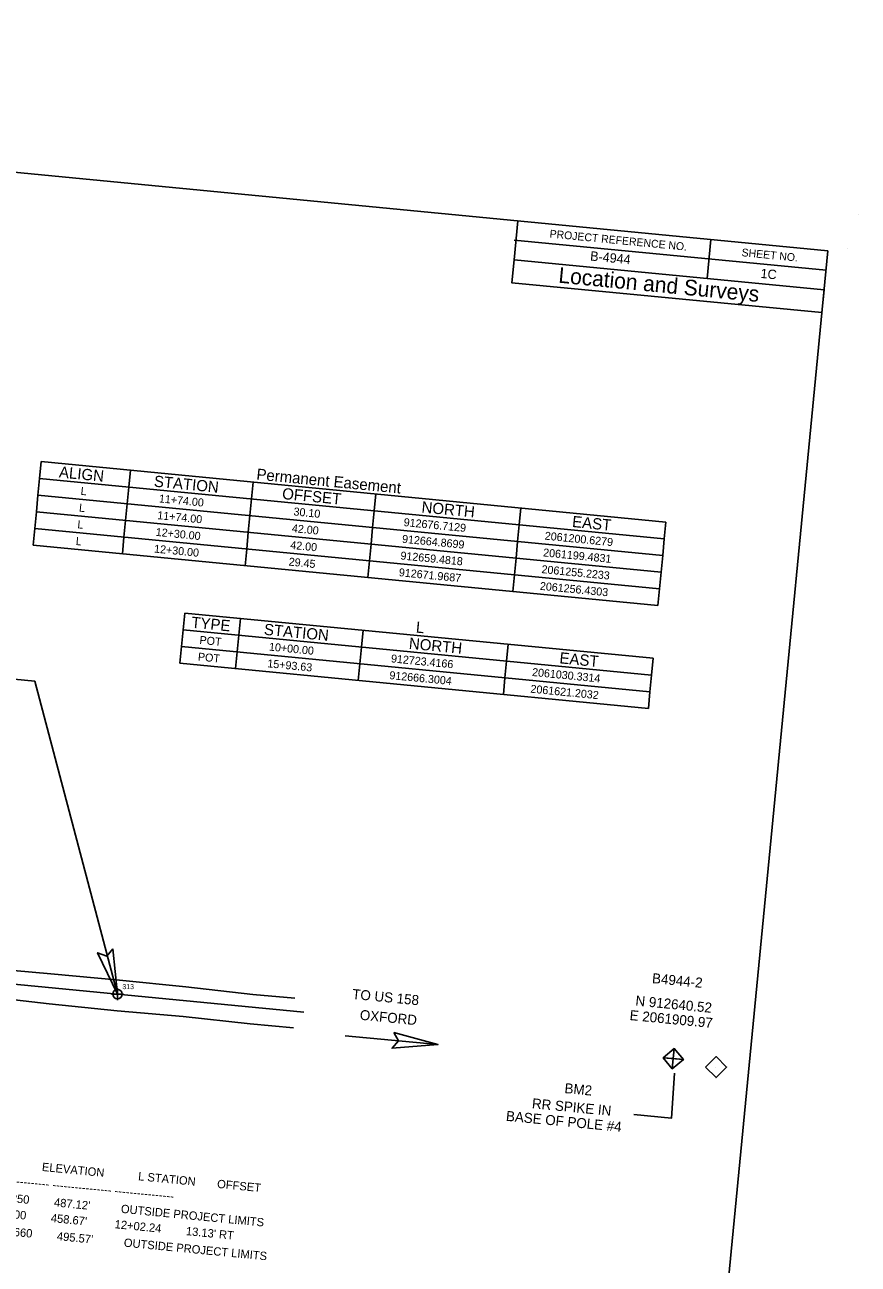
# Model space of a CAD drawing. Extents: x 2060504 to 2061945, y 912229 to 913160.
# Drawn here: x 2061482 to 2061898, y 912540 to 913160 of the extents above; entities that cross this region are included whole.
import ezdxf

# ---------------------------------------------------------------- set-up
doc = ezdxf.new("R2010")
doc.units = 0
for name, color, linetype in [('COGO Default Chain', 7, 'Continuous'), ('Cogo Default Point CELL', 7, 'Continuous'), ('COGO Default Point Number', 7, 'Continuous'), ('CTL Bench Mark CELL', 7, 'Continuous'), ('CTL Bench Mark Leader', 7, 'Continuous'), ('CTL Bench Mark Text', 7, 'Continuous'), ('CTL Sheet Border CELL', 7, 'Continuous'), ('CTL Sheet Notes CELL', 7, 'Continuous'), ('CTL Sheet Table Cell', 7, 'Continuous'), ('CTL Sheet Text', 7, 'Continuous'), ('CTL Supplemental Horizontal and Vertical CELL', 7, 'Continuous'), ('CTL Supplemental Horizontal and Vertical Text', 7, 'Continuous'), ('Exist Horizontal Alignment', 7, 'Continuous'), ('Exist Roads Soil', 7, 'Continuous'), ('Prop Terminator CELL', 7, 'Continuous'), ('Sheet Data Field CELL', 7, 'Continuous')]:
    doc.layers.add(name, color=color, linetype=linetype)

# ---------------------------------------------------------------- blocks, each defined once
blk = doc.blocks.new('COGO DEFAULT POINT')
at = {"layer": 'Cogo Default Point CELL'}
for points in [[(-0.06, 0), (0, 0)], [(0, 0.06), (0, 0)], [(0, 0), (0.06, 0)], [(0, 0), (0, -0.06)]]:
    blk.add_lwpolyline(points, dxfattribs=at)
blk.add_circle((0, 0), 0.0469, dxfattribs=at)

msp = doc.modelspace()

# ---------------------------------------------------------------- linework, layer by layer
at = {"layer": 'COGO Default Chain'}
msp.add_line((2061030.33, 912723.42), (2061621.2, 912666.3), dxfattribs=at)
at = {"layer": 'CTL Bench Mark CELL'}
msp.add_line((2061805.75, 912643.06), (2061805.75, 912643.06), dxfattribs=at)
msp.add_lwpolyline([(2061800.69, 912643.54), (2061806.23, 912648.11), (2061810.8, 912642.57), (2061805.26, 912638)], close=True, dxfattribs=at)
for points in [[(2061806.23, 912648.11), (2061805.26, 912638), (2061805.74, 912643.06), (2061810.8, 912642.57), (2061800.69, 912643.54)], [(2061805.74, 912643.06), (2061806.23, 912648.11), (2061800.69, 912643.54), (2061805.74, 912643.06)], [(2061805.74, 912643.06), (2061805.26, 912638), (2061810.8, 912642.57), (2061805.74, 912643.06)]]:
    msp.add_lwpolyline(points, dxfattribs=at)
at = {"layer": 'CTL Bench Mark Leader'}
msp.add_lwpolyline([(2061806.34, 912635.72), (2061804.9, 912613.3), (2061786.04, 912615.13)], dxfattribs=at)
at = {"layer": 'CTL Sheet Border CELL'}
for p, q in [((2061898.13, 913065.22), (2061898.13, 913065.22)), ((2061728.05, 913061.97), (2061726.16, 913042.5)), ((2061726.22, 913052.31), (2061882.06, 913037.25)), ((2061824.58, 913052.64), (2061822.7, 913033.17)), ((2061892.94, 913048.08), (2061892.94, 913048.08)), ((2061892.94, 913048.08), (2061892.94, 913048.08))]:
    msp.add_line(p, q, dxfattribs=at)
for points in [[(2061883, 913047.03), (2060714.54, 913159.97), (2060635.47, 912342.05), (2061803.94, 912229.1)], [(2061726.16, 913042.5), (2061881.12, 913027.52), (2061880.01, 913016.05), (2061725.06, 913031.03)]]:
    msp.add_lwpolyline(points, close=True, dxfattribs=at)
at = {"layer": 'CTL Sheet Table Cell'}
for p, q in [((2061489.92, 912941.54), (2061489.11, 912933.18)), ((2061489.92, 912941.54), (2061802.07, 912911.37)), ((2061534.51, 912937.23), (2061533.7, 912928.87)), ((2061489.11, 912933.18), (2061488.3, 912924.82)), ((2061489.11, 912933.18), (2061801.26, 912903.01)), ((2061533.7, 912928.87), (2061532.9, 912920.51)), ((2061595.83, 912931.31), (2061595.02, 912922.95)), ((2061488.3, 912924.82), (2061487.5, 912916.46)), ((2061488.3, 912924.82), (2061800.45, 912894.65)), ((2061595.02, 912922.95), (2061594.21, 912914.58)), ((2061657.14, 912925.38), (2061656.33, 912917.02)), ((2061487.5, 912916.46), (2061486.69, 912908.1)), ((2061487.5, 912916.46), (2061799.64, 912886.29)), ((2061532.9, 912920.51), (2061532.09, 912912.15)), ((2061656.33, 912917.02), (2061655.52, 912908.66)), ((2061729.6, 912918.38), (2061728.79, 912910.01)), ((2061532.09, 912912.15), (2061531.28, 912903.79)), ((2061594.21, 912914.58), (2061593.4, 912906.22)), ((2061728.79, 912910.01), (2061727.99, 912901.65)), ((2061802.07, 912911.37), (2061801.26, 912903.01)), ((2061486.69, 912908.1), (2061485.88, 912899.74)), ((2061486.69, 912908.1), (2061798.83, 912877.93)), ((2061531.28, 912903.79), (2061530.47, 912895.43)), ((2061593.4, 912906.22), (2061592.59, 912897.86)), ((2061655.52, 912908.66), (2061654.72, 912900.3)), ((2061801.26, 912903.01), (2061800.45, 912894.65)), ((2061485.88, 912899.74), (2061798.02, 912869.57)), ((2061592.59, 912897.86), (2061591.79, 912889.5)), ((2061654.72, 912900.3), (2061653.91, 912891.94)), ((2061727.99, 912901.65), (2061727.18, 912893.29)), ((2061653.91, 912891.94), (2061653.1, 912883.57)), ((2061727.18, 912893.29), (2061726.37, 912884.93)), ((2061800.45, 912894.65), (2061799.64, 912886.29)), ((2061726.37, 912884.93), (2061725.56, 912876.57)), ((2061799.64, 912886.29), (2061798.83, 912877.93)), ((2061798.83, 912877.93), (2061798.02, 912869.57)), ((2061561.62, 912865.85), (2061560.81, 912857.49)), ((2061561.62, 912865.85), (2061795.73, 912843.22)), ((2061589.49, 912863.16), (2061588.68, 912854.79)), ((2061560.81, 912857.49), (2061560, 912849.13)), ((2061560.81, 912857.49), (2061794.92, 912834.86)), ((2061588.68, 912854.79), (2061587.87, 912846.43)), ((2061650.8, 912857.23), (2061650, 912848.87)), ((2061560, 912849.13), (2061559.2, 912840.77)), ((2061560, 912849.13), (2061794.11, 912826.5)), ((2061650, 912848.87), (2061649.19, 912840.51)), ((2061723.27, 912850.22), (2061722.46, 912841.86)), ((2061587.87, 912846.43), (2061587.07, 912838.07)), ((2061722.46, 912841.86), (2061721.65, 912833.5)), ((2061795.73, 912843.22), (2061794.92, 912834.86)), ((2061559.2, 912840.77), (2061793.3, 912818.14)), ((2061649.19, 912840.51), (2061648.38, 912832.15)), ((2061794.92, 912834.86), (2061794.11, 912826.5)), ((2061721.65, 912833.5), (2061720.84, 912825.14)), ((2061794.11, 912826.5), (2061793.3, 912818.14))]:
    msp.add_line(p, q, dxfattribs=at)
at = {"layer": 'CTL Supplemental Horizontal and Vertical CELL'}
msp.add_line((2061827.08, 912638.82), (2061827.08, 912638.82), dxfattribs=at)
msp.add_lwpolyline([(2061821.86, 912638.84), (2061827.1, 912644.08), (2061832.35, 912638.83), (2061827.11, 912633.59)], close=True, dxfattribs=at)
at = {"layer": 'Exist Horizontal Alignment'}
msp.add_line((2061030.33, 912723.42), (2061621.2, 912666.3), dxfattribs=at)
at = {"layer": 'Exist Roads Soil'}
for p, q in [((2061458.76, 912674.47), (2061493.97, 912670.51)), ((2061493.97, 912670.51), (2061527.89, 912666.97)), ((2061527.89, 912666.97), (2061560.93, 912664.14)), ((2061560.93, 912664.14), (2061594.28, 912660.42)), ((2061594.28, 912660.42), (2061615.94, 912658.44))]:
    msp.add_line(p, q, dxfattribs=at)
msp.add_lwpolyline([(2061616.65, 912673.35), (2061595.6, 912675.15), (2061562.27, 912678.91), (2061528.97, 912682.23), (2061494.66, 912685.54), (2061457.3, 912688.8)], dxfattribs=at)
at = {"layer": 'Prop Terminator CELL'}
for points in [[(2061525.73, 912698.03), (2061528.01, 912675.31), (2061518.11, 912696.04), (2061522.73, 912694.34)], [(2061666.15, 912656.07), (2061688.18, 912650.05), (2061665.27, 912648.25), (2061668.52, 912651.95)]]:
    msp.add_lwpolyline(points, close=True, dxfattribs=at)
at = {"layer": 'Sheet Data Field CELL'}
for p, q in [((2061344.47, 912845.53), (2061486.76, 912831.77)), ((2061486.76, 912831.77), (2061528.01, 912675.31)), ((2061641.77, 912654.54), (2061688.18, 912650.05))]:
    msp.add_line(p, q, dxfattribs=at)

# ---------------------------------------------------------------- block references
at = {"layer": 'Cogo Default Point CELL', "xscale": 50, "yscale": 50}
msp.add_blockref('COGO DEFAULT POINT', (2061528.01, 912675.31), dxfattribs=at)

# ---------------------------------------------------------------- texts
at = {"layer": 'COGO Default Point Number'}
msp.add_text('313', height=2.5, dxfattribs=at).set_placement((2061530.51, 912677.81))
at = {"layer": 'CTL Bench Mark Text'}
for s, p in [('BM2', (2061751.23, 912625.87)), ('RR SPIKE IN ', (2061734.96, 912618.28)), ('BASE OF POLE #4', (2061721.98, 912612))]:
    msp.add_text(s, height=5, rotation=354.47872, dxfattribs=at).set_placement(p)
at = {"layer": 'CTL Sheet Border CELL'}
for s, height, p in [('PROJECT REFERENCE NO.', 3.9131, (2061743.82, 913053.64)), ('B-4944', 4.696, (2061764.04, 913042.14)), ('SHEET NO.', 3.913, (2061839.75, 913044.29)), ('Location and Surveys', 7.8262, (2061748.14, 913031.07)), ('1C', 4.696, (2061849.18, 913033.43))]:
    msp.add_text(s, height=height, rotation=354.4787, dxfattribs=at).set_placement(p)
at = {"layer": 'CTL Sheet Notes CELL'}
for s, p in [('ALIGN', (2061498.64, 912933.67)), ('STATION', (2061546.06, 912929.08)), ('Permanent Easement', (2061597.28, 912932.57)), ('OFFSET', (2061610.14, 912922.89)), ('NORTH', (2061679.79, 912916.16)), ('EAST', (2061755.02, 912908.89)), ('TYPE', (2061564.74, 912858.51)), ('STATION', (2061601.04, 912855.01)), ('L', (2061676.97, 912856.11)), ('NORTH', (2061673.46, 912848.01)), ('EAST', (2061748.69, 912840.73))]:
    msp.add_text(s, height=5.6, rotation=354.4787, dxfattribs=at).set_placement(p)
at = {"layer": 'CTL Sheet Text'}
for s, height, p in [('L', 4, (2061509.49, 912924.98)), ('11+74.00', 4, (2061548.62, 912921.2)), ('L', 4, (2061508.69, 912916.62)), ('11+74.00', 4, (2061547.81, 912912.84)), ('30.10', 4, (2061615.86, 912914.7)), ('L', 4, (2061507.88, 912908.26)), ('42.00', 4, (2061615.05, 912906.34)), ('912676.7129', 4, (2061670.9, 912909.38)), ('L', 4, (2061507.07, 912899.9)), ('12+30.00', 4, (2061547.01, 912904.48)), ('912664.8699', 4, (2061670.09, 912901.02)), ('2061200.6279', 4, (2061741.39, 912902.57)), ('12+30.00', 4, (2061546.2, 912896.12)), ('42.00', 4, (2061614.25, 912897.98)), ('2061199.4831', 4, (2061740.58, 912894.21)), ('29.45', 4, (2061613.44, 912889.62)), ('912659.4818', 4, (2061669.28, 912892.66)), ('912671.9687', 4, (2061668.48, 912884.3)), ('2061255.2233', 4, (2061739.77, 912885.85)), ('2061256.4303', 4, (2061738.96, 912877.49)), ('POT', 4, (2061568.88, 912850.48)), ('10+00.00', 4, (2061603.6, 912847.12)), ('POT', 4, (2061568.08, 912842.12)), ('15+93.63', 4, (2061602.79, 912838.76)), ('912723.4166', 4, (2061664.56, 912841.23)), ('912666.3004', 4, (2061663.76, 912832.87)), ('2061030.3314', 4, (2061735.05, 912834.42)), ('2061621.2032', 4, (2061734.24, 912826.06)), ('    POINT          DESC.           NORTH             EAST          ELEVATION           L STATION       OFFSET', 4.16667, (2061348.09, 912600.65)), ('------------ ---------------- ---------------- ---------------- ---------------- ---------------- ----------------', 4.16667, (2061347.29, 912592.36)), ("     1           B4944-1         912752.0851     2060519.4250        487.12'          OUTSIDE PROJECT LIMITS                 ", 4.16667, (2061345.7, 912583.76)), ("   201              BL-1         912690.8878     2061230.3700        458.67'         12+02.24        13.13' RT", 4.16667, (2061345.68, 912575.77)), ("   202           B4944-2         912640.5229     2061909.9660        495.57'          OUTSIDE PROJECT LIMITS                 ", 4.16667, (2061344.09, 912567.17))]:
    msp.add_text(s, height=height, rotation=354.4787, dxfattribs=at).set_placement(p)
at = {"layer": 'CTL Supplemental Horizontal and Vertical Text'}
for s, p in [('B4944-2', (2061794.97, 912680.86)), ('N 912640.52', (2061786.68, 912669.64)), ('E 2061909.97', (2061783.77, 912662.38))]:
    msp.add_text(s, height=5, rotation=354.47872, dxfattribs=at).set_placement(p)
at = {"layer": 'Sheet Data Field CELL'}
for s, p in [('TO US 158', (2061645.15, 912672.94)), ('OXFORD', (2061648.95, 912662.53))]:
    msp.add_text(s, height=5, rotation=354.4787, dxfattribs=at).set_placement(p)

doc.saveas('drawing.dxf')
